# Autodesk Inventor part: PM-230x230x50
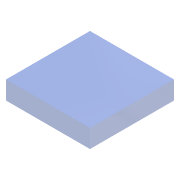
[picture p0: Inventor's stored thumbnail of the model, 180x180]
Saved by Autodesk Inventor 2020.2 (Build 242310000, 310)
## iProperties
Created: 2015-11
Part Number: PM-230x230x50
Material: Ogólny
Document SubType Name: Modeling
Designer: F.Stasiak
Density: 1 g/cm^3
Appearance: Przezroczysty - niebieski
Catalog Web Link: www.expertbooks.pl
Manager: www.cadconsulting.pl
Company: Fabian Stasiak CAD Consulting
Author: F.Stasiak
Subject: Zbiór ćwiczeń. Autodesk Inventor 2020. Kurs Professional
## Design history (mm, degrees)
sketch "Szkic1"
  geometry: L1 (-115, 115)-(115, 115); L2 (115, 115)-(115, -115); L3 (115, -115)-(-115, -115); L4 (-115, -115)-(-115, 115); L5 (-115, 115)-(115, -115); L6 (115, 115)-(-115, -115); 1 further point
  constraints: 12 end point, 2 midpoint, 2 parallel, 1 horizontal, 1 perpendicular
  dimensions: "d0" = 230 distance of L2.end L3.end; "d1" = 230 distance of L1.end L2.end
extrude "Wyciągnięcie proste1" new body sketch "Szkic1" distance "d2" = 50; taper "d3" = 0 deg
node "Bryła1"
